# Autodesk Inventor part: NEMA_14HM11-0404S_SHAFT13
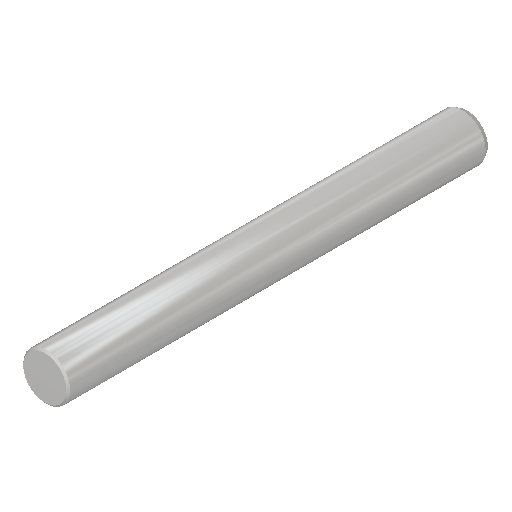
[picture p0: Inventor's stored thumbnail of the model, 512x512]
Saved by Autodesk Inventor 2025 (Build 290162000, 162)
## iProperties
Created: 2019-11
Part Number: NEMA_14HM11-0404S_SHAFT13
Material: Générique
Document SubType Name: Modeling
Designer: thoma
Density: 1 g/cm^3
Appearance: Aluminium - Plat
Author: thoma
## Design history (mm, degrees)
sketch "Esquisse1"
  geometry: C1 r 2.5 at (0, 0); 1 further point
  constraints: 1 centre point, 1 coincident
  dimensions: "d0" = 5 diameter of C1
extrude "Extrusion1" new body sketch "Esquisse1" distance "d1" = 45; taper "d2" = 0 deg
chamfer "Chanfrein1" distance "d3" = 0.2; stored, may be unused: second distance "d4" = 2, angle "d5" = 45 deg
chamfer "Chanfrein2" distance "d6" = 0.3; stored, may be unused: second distance "d7" = 2, angle "d8" = 60 deg
sketch "Esquisse2"
  geometry: L1 (-2.5, 0)-(2, 0); L2 (2, 0)-(2, 1.5); L3 (2, 0)-(2, -1.5); A1 r 2.5 centre (0, 0) between (2, -1.5) and (2, 1.5); 2 further points
  constraints: 6 end point, 2 point on circle, 1 centre point, 1 coincident, 1 horizontal, 1 horizontal alignment, 1 point on line, 1 vertical, 1 other
  dimensions: "d9" = 4.5 distance of L1.start L1.end
extrude "Extrusion2" cut sketch "Esquisse2" distance "d10" = 15; taper "d11" = 0 deg
fillet "Congé1" dims "d12" = 0.1
node "Solide1"
